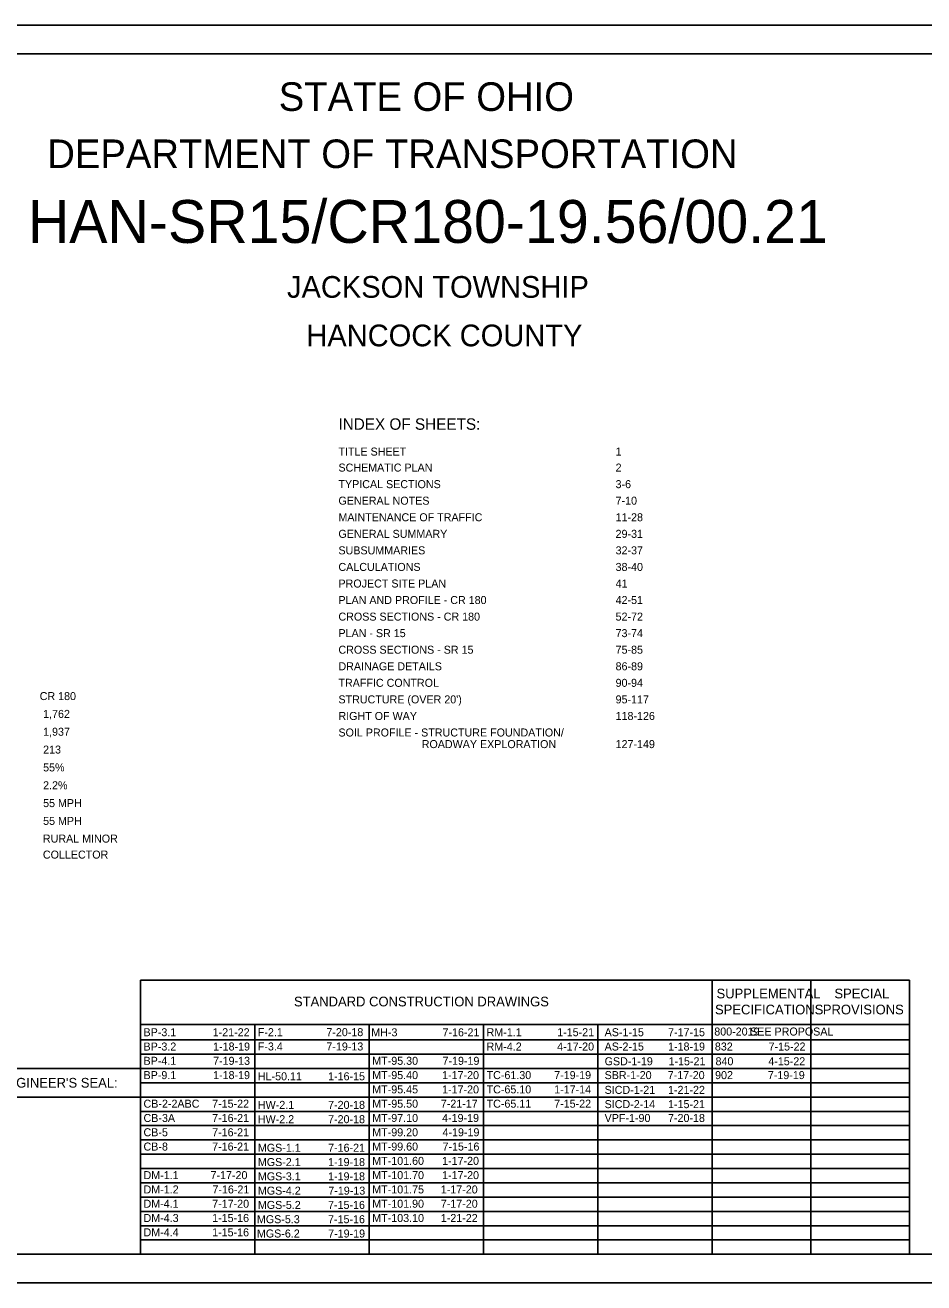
# Model space of a CAD drawing. Extents: x 0 to 45.5, y 0 to 22.
# Drawn here: x 9.53 to 25.25, y 0 to 22 of the extents above; entities that cross this region are included whole.
import ezdxf

# ---------------------------------------------------------------- set-up
doc = ezdxf.new("R2010")
doc.units = 0
for name, color, linetype in [('Default', 7, 'Continuous'), ('SH_Border', 7, 'Continuous'), ('SH_Cut_Line', 7, 'Continuous'), ('SH_Data', 7, 'Continuous'), ('SH_Text', 7, 'Continuous')]:
    doc.layers.add(name, color=color, linetype=linetype)

msp = doc.modelspace()

# ---------------------------------------------------------------- linework, layer by layer
at = {"layer": 'SH_Border'}
msp.add_lwpolyline([(1.5, 21.5), (33.5, 21.5), (33.5, 0.5), (1.5, 0.5)], close=True, dxfattribs=at)
at = {"layer": 'SH_Cut_Line'}
msp.add_lwpolyline([(0, 0), (34, 0), (34, 22), (0, 22)], close=True, dxfattribs=at)
at = {"layer": 'SH_Data'}
for p, q in [((11.55, 5.292), (25, 5.292)), ((11.55, 0.5), (11.55, 5.292)), ((21.55, 0.5), (21.55, 5.292)), ((23.275, 0.5), (23.275, 5.292)), ((25, 0.5), (25, 5.292)), ((11.55, 4.521), (25, 4.521)), ((13.55, 0.5), (13.55, 4.521)), ((15.55, 0.5), (15.55, 4.521)), ((17.55, 0.5), (17.55, 4.521)), ((19.55, 0.5), (19.55, 4.521)), ((11.55, 4.25), (25, 4.25)), ((11.55, 4), (25, 4)), ((8.75, 3.75), (11.55, 3.75)), ((11.55, 3.75), (25, 3.75)), ((11.55, 3.5), (25, 3.5)), ((8.75, 3.25), (11.55, 3.25)), ((11.55, 3.25), (25, 3.25)), ((11.55, 3), (25, 3)), ((11.55, 2.75), (25, 2.75)), ((11.55, 2.5), (25, 2.5)), ((11.55, 2.25), (25, 2.25)), ((11.55, 2), (25, 2)), ((11.55, 1.75), (25, 1.75)), ((11.55, 1.5), (25, 1.5)), ((11.55, 1.25), (25, 1.25)), ((11.55, 1), (25, 1)), ((11.55, 0.75), (25, 0.75))]:
    msp.add_line(p, q, dxfattribs=at)

# ---------------------------------------------------------------- texts
at = {"layer": 'Default'}
for s, height, p in [('STATE OF OHIO', 0.5, (13.968, 20.5)), ('DEPARTMENT OF TRANSPORTATION', 0.5, (9.92, 19.5)), ('HAN-SR15/CR180-19.56/00.21', 0.75, (9.579, 18.191)), ('JACKSON TOWNSHIP', 0.38, (14.112, 17.231)), ('HANCOCK COUNTY', 0.38, (14.451, 16.382)), ("ENGINEER'S SEAL:", 0.17, (9.06, 3.415))]:
    msp.add_text(s, height=height, dxfattribs=at).set_placement(p)
at = {"layer": 'SH_Data'}
for s, height, p in [('INDEX OF SHEETS:', 0.2, (15.012, 14.922)), ('TITLE SHEET', 0.14, (15.012, 14.471)), ('1', 0.14, (19.859, 14.471)), ('SCHEMATIC PLAN', 0.14, (15.012, 14.191)), ('2', 0.14, (19.859, 14.191)), ('TYPICAL SECTIONS', 0.14, (15.012, 13.901)), ('3-6', 0.14, (19.859, 13.901)), ('GENERAL NOTES', 0.14, (15.012, 13.612)), ('7-10', 0.14, (19.859, 13.612)), ('MAINTENANCE OF TRAFFIC', 0.14, (15.012, 13.322)), ('11-28', 0.14, (19.859, 13.322)), ('GENERAL SUMMARY', 0.14, (15.012, 13.032)), ('29-31', 0.14, (19.859, 13.032)), ('SUBSUMMARIES', 0.14, (15.012, 12.743)), ('32-37', 0.14, (19.859, 12.743)), ('CALCULATIONS', 0.14, (15.012, 12.453)), ('38-40', 0.14, (19.859, 12.453)), ('PROJECT SITE PLAN', 0.14, (15.012, 12.163)), ('41', 0.14, (19.859, 12.163)), ('PLAN AND PROFILE - CR 180 ', 0.14, (15.012, 11.874)), ('42-51', 0.14, (19.859, 11.874)), ('CROSS SECTIONS - CR 180', 0.14, (15.012, 11.584)), ('52-72', 0.14, (19.859, 11.584)), ('PLAN - SR 15', 0.14, (15.012, 11.295)), ('73-74', 0.14, (19.859, 11.295)), ('CROSS SECTIONS - SR 15', 0.14, (15.012, 11.005)), ('75-85', 0.14, (19.859, 11.005)), ('DRAINAGE DETAILS', 0.14, (15.012, 10.715)), ('86-89', 0.14, (19.859, 10.715)), ('TRAFFIC CONTROL', 0.14, (15.012, 10.426)), ('90-94', 0.14, (19.859, 10.426)), ("STRUCTURE (OVER 20')", 0.14, (15.012, 10.136)), ('95-117', 0.14, (19.859, 10.136)), ('1,762', 0.14, (9.847, 9.882)), ('RIGHT OF WAY', 0.14, (15.012, 9.846)), ('118-126', 0.14, (19.859, 9.846)), ('1,937', 0.14, (9.847, 9.57)), ('SOIL PROFILE - STRUCTURE FOUNDATION/', 0.14, (15.012, 9.557)), ('                            ROADWAY EXPLORATION', 0.14, (15.012, 9.354)), ('127-149', 0.14, (19.859, 9.354)), ('213', 0.14, (9.847, 9.258)), ('55%', 0.14, (9.847, 8.946)), ('2.2%', 0.14, (9.847, 8.634)), ('55 MPH', 0.14, (9.847, 8.322)), ('55 MPH', 0.14, (9.847, 8.01)), ('RURAL MINOR', 0.14, (9.843, 7.701)), ('COLLECTOR', 0.14, (9.843, 7.421)), ('SUPPLEMENTAL', 0.17, (21.624, 4.976)), ('SPECIAL', 0.17, (23.686, 4.976)), ('STANDARD CONSTRUCTION DRAWINGS', 0.17, (14.234, 4.836)), ('SPECIFICATIONS', 0.17, (21.598, 4.696)), ('PROVISIONS', 0.17, (23.484, 4.696)), ('BP-3.1', 0.14, (11.603, 4.314)), ('1-21-22', 0.14, (12.813, 4.314)), ('F-2.1', 0.14, (13.602, 4.315)), ('7-20-18', 0.14, (14.801, 4.315)), ('MH-3', 0.14, (15.586, 4.312)), ('7-16-21', 0.14, (16.832, 4.312)), ('RM-1.1', 0.14, (17.603, 4.314)), ('1-15-21', 0.14, (18.838, 4.314)), ('AS-1-15', 0.14, (19.667, 4.314)), ('7-17-15', 0.14, (20.777, 4.314)), ('800-2019', 0.14, (21.585, 4.326)), ('SEE PROPOSAL', 0.14, (22.212, 4.326)), ('BP-3.2', 0.14, (11.603, 4.064)), ('1-18-19', 0.14, (12.82, 4.064)), ('F-3.4', 0.14, (13.602, 4.065)), ('7-19-13', 0.14, (14.801, 4.065)), ('RM-4.2', 0.14, (17.603, 4.064)), ('4-17-20', 0.14, (18.837, 4.064)), ('AS-2-15', 0.14, (19.667, 4.064)), ('1-18-19', 0.14, (20.777, 4.064)), ('832', 0.14, (21.595, 4.064)), ('7-15-22', 0.14, (22.535, 4.064)), ('BP-4.1', 0.14, (11.603, 3.814)), ('7-19-13', 0.14, (12.82, 3.814)), ('MT-95.30', 0.14, (15.603, 3.814)), ('7-19-19', 0.14, (16.832, 3.814)), ('GSD-1-19', 0.14, (19.667, 3.806)), ('1-15-21', 0.14, (20.785, 3.806)), ('840', 0.14, (21.607, 3.806)), ('4-15-22', 0.14, (22.53, 3.806)), ('BP-9.1', 0.14, (11.603, 3.564)), ('1-18-19', 0.14, (12.82, 3.564)), ('HL-50.11', 0.14, (13.603, 3.543)), ('1-16-15', 0.14, (14.831, 3.543)), ('MT-95.40', 0.14, (15.603, 3.564)), ('1-17-20', 0.14, (16.825, 3.564)), ('TC-61.30', 0.14, (17.603, 3.564)), ('7-19-19', 0.14, (18.785, 3.564)), ('SBR-1-20', 0.14, (19.667, 3.564)), ('7-17-20', 0.14, (20.771, 3.564)), ('902', 0.14, (21.599, 3.564)), ('7-19-19', 0.14, (22.522, 3.564)), ('MT-95.45', 0.14, (15.603, 3.314)), ('1-17-20', 0.14, (16.825, 3.314)), ('TC-65.10', 0.14, (17.603, 3.314)), ('1-17-14', 0.14, (18.785, 3.314)), ('SICD-1-21', 0.14, (19.667, 3.306)), ('1-21-22', 0.14, (20.776, 3.306)), ('CB-2-2ABC', 0.14, (11.603, 3.064)), ('7-15-22', 0.14, (12.803, 3.064)), ('HW-2.1', 0.14, (13.603, 3.043)), ('7-20-18', 0.14, (14.831, 3.043)), ('MT-95.50', 0.14, (15.603, 3.064)), ('7-21-17', 0.14, (16.802, 3.064)), ('TC-65.11', 0.14, (17.603, 3.064)), ('7-15-22', 0.14, (18.785, 3.064)), ('SICD-2-14', 0.14, (19.667, 3.056)), ('1-15-21', 0.14, (20.776, 3.056)), ('CB-3A', 0.14, (11.603, 2.814)), ('7-16-21', 0.14, (12.803, 2.814)), ('HW-2.2', 0.14, (13.603, 2.793)), ('7-20-18', 0.14, (14.831, 2.793)), ('MT-97.10', 0.14, (15.603, 2.814)), ('4-19-19', 0.14, (16.825, 2.814)), ('VPF-1-90', 0.14, (19.667, 2.814)), ('7-20-18', 0.14, (20.776, 2.814)), ('CB-5', 0.14, (11.603, 2.564)), ('7-16-21', 0.14, (12.803, 2.564)), ('MT-99.20', 0.14, (15.603, 2.564)), ('4-19-19', 0.14, (16.832, 2.564)), ('CB-8', 0.14, (11.603, 2.314)), ('7-16-21', 0.14, (12.803, 2.314)), ('MGS-1.1', 0.14, (13.603, 2.293)), ('7-16-21', 0.14, (14.831, 2.293)), ('MT-99.60', 0.14, (15.603, 2.314)), ('7-15-16', 0.14, (16.832, 2.314)), ('MT-101.60', 0.14, (15.603, 2.064)), ('1-17-20', 0.14, (16.825, 2.064)), ('MGS-2.1', 0.14, (13.603, 2.043)), ('1-19-18', 0.14, (14.831, 2.043)), ('DM-1.1', 0.14, (11.603, 1.814)), ('7-17-20', 0.14, (12.775, 1.814)), ('MGS-3.1', 0.14, (13.603, 1.793)), ('1-19-18', 0.14, (14.831, 1.793)), ('MT-101.70', 0.14, (15.603, 1.814)), ('1-17-20', 0.14, (16.825, 1.814)), ('DM-1.2', 0.14, (11.603, 1.564)), ('7-16-21', 0.14, (12.808, 1.564)), ('MGS-4.2', 0.14, (13.603, 1.543)), ('7-19-13', 0.14, (14.835, 1.543)), ('MT-101.75', 0.14, (15.603, 1.564)), ('1-17-20', 0.14, (16.802, 1.564)), ('DM-4.1', 0.14, (11.603, 1.314)), ('7-17-20', 0.14, (12.804, 1.314)), ('MGS-5.2', 0.14, (13.603, 1.293)), ('7-15-16', 0.14, (14.83, 1.293)), ('MT-101.90', 0.14, (15.603, 1.314)), ('7-17-20', 0.14, (16.802, 1.314)), ('DM-4.3', 0.14, (11.603, 1.064)), ('1-15-16', 0.14, (12.803, 1.064)), ('MGS-5.3', 0.14, (13.586, 1.043)), ('7-15-16', 0.14, (14.83, 1.043)), ('MT-103.10', 0.14, (15.603, 1.064)), ('1-21-22', 0.14, (16.802, 1.064)), ('DM-4.4', 0.14, (11.603, 0.814)), ('1-15-16', 0.14, (12.803, 0.814)), ('MGS-6.2', 0.14, (13.586, 0.793)), ('7-19-19', 0.14, (14.832, 0.793))]:
    msp.add_text(s, height=height, dxfattribs=at).set_placement(p)
at = {"layer": 'SH_Text'}
msp.add_text('CR 180', height=0.14, dxfattribs=at).set_placement((9.787, 10.194))

doc.saveas('drawing.dxf')
